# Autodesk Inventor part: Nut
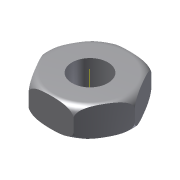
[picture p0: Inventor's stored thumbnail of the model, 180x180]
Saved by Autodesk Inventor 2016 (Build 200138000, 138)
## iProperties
Created: 2009-04
Part Number: Nut
Document SubType Name: Modeling
Designer: Sham
Density: 1 g/cm^3
Material: Generic
Appearance: Default
Author: Sham
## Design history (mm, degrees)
sketch "Sketch1"
  geometry: L1 (7.5, 12.99)-(15, 0); L2 (15, 0)-(7.5, -12.99); L3 (7.5, -12.99)-(-7.5, -12.99); L4 (-7.5, -12.99)-(-15, 0); L5 (-15, 0)-(-7.5, 12.99); L6 (-7.5, 12.99)-(7.5, 12.99); C1 r 6 at (0, 0); 1 further point
  constraints: 12 end point, 1 centre point, 1 coincident, 13 other
  dimensions: "d0" = 30 distance of L1.end L4.end; "d1" = 12 diameter of C1
extrude "Extrusion1" new body sketch "Sketch1" distance "d2" = 12; taper "d3" = 0 deg
sketch "Sketch2"
  geometry: L1 (-12, 0)-(-12, -0.022); L2 (-15, 7)-(-15, 3); L3 (0, -2.87)-(0, 12.87) reference; A1 r 3 centre (-12, 7) between (-12, 10) and (-15, 7); A2 r 3 centre (-12, 3) between (-15, 3) and (-12, 0)
  constraints: 4 end point, 4 point on circle, 2 centre point, 1 tangent
revolve "Revolution1" sketch "Sketch2" stored, may be unused: angle "d7" = 90 deg
body "Solid1"
other parameters: "d6" = 90 deg
